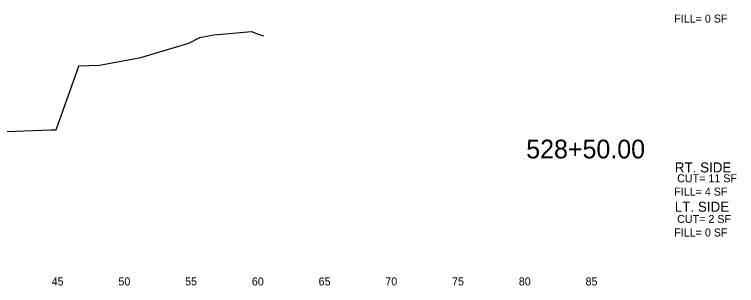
# Model space of a CAD drawing. Extents: x -4 to 359, y 0 to 1436.
# Drawn here: x 85.7 to 139.8, y 150.5 to 170.8 of the extents above; entities that cross this region are included whole.
import ezdxf

# ---------------------------------------------------------------- set-up
doc = ezdxf.new("R2010")
doc.units = 0
for name, color, linetype in [('XS-Existing surface-ground', 7, 'Continuous'), ('XS-Text-earthwork labels', 7, 'Continuous'), ('XS-Text-offset label', 7, 'Continuous')]:
    doc.layers.add(name, color=color, linetype=linetype)

msp = doc.modelspace()

# ---------------------------------------------------------------- linework, layer by layer
at = {"layer": 'XS-Existing surface-ground'}
for p, q in [((100.643, 169.258), (103.454, 169.501)), ((103.454, 169.501), (104.028, 169.282)), ((98.758, 168.632), (99.595, 169.046)), ((99.595, 169.046), (100.643, 169.258)), ((104.028, 169.282), (104.363, 169.182)), ((95.169, 167.569), (98.758, 168.632)), ((92.061, 166.988), (95.169, 167.569)), ((90.398, 166.565), (90.511, 166.931)), ((90.511, 166.931), (92.061, 166.988)), ((88.812, 162.15), (90.398, 166.565)), ((80.588, 161.862), (88.435, 162.148)), ((88.435, 162.148), (88.812, 162.15))]:
    msp.add_line(p, q, dxfattribs=at)

# ---------------------------------------------------------------- texts
at = {"layer": 'XS-Text-earthwork labels'}
for s, height, p in [('FILL= 0 SF           ', 0.6, (135.125, 170.171)), ('RT. SIDE', 0.75, (135.171, 158.954)), (' CUT= 11 SF           ', 0.6, (135.125, 158.216)), ('FILL= 4 SF           ', 0.6, (135.125, 157.218)), ('LT. SIDE', 0.75, (135.171, 156.012)), (' CUT= 2 SF           ', 0.6, (135.125, 155.171)), ('FILL= 0 SF           ', 0.6, (135.125, 154.158))]:
    msp.add_text(s, height=height, dxfattribs=at).set_placement(p)
at = {"layer": 'XS-Text-offset label'}
for s, height, p in [('           528+50.00           ', 1.4, (118.317, 160.005)), ('           45           ', 0.6, (86.03, 150.495)), ('           50           ', 0.6, (91.03, 150.495)), ('           55           ', 0.6, (96.03, 150.495)), ('           60           ', 0.6, (101.03, 150.495)), ('           65           ', 0.6, (106.03, 150.495)), ('           70           ', 0.6, (111.03, 150.495)), ('           75           ', 0.6, (116.03, 150.495)), ('           80           ', 0.6, (121.03, 150.495)), ('           85           ', 0.6, (126.03, 150.495))]:
    msp.add_text(s, height=height, dxfattribs=at).set_placement(p)

doc.saveas('drawing.dxf')
